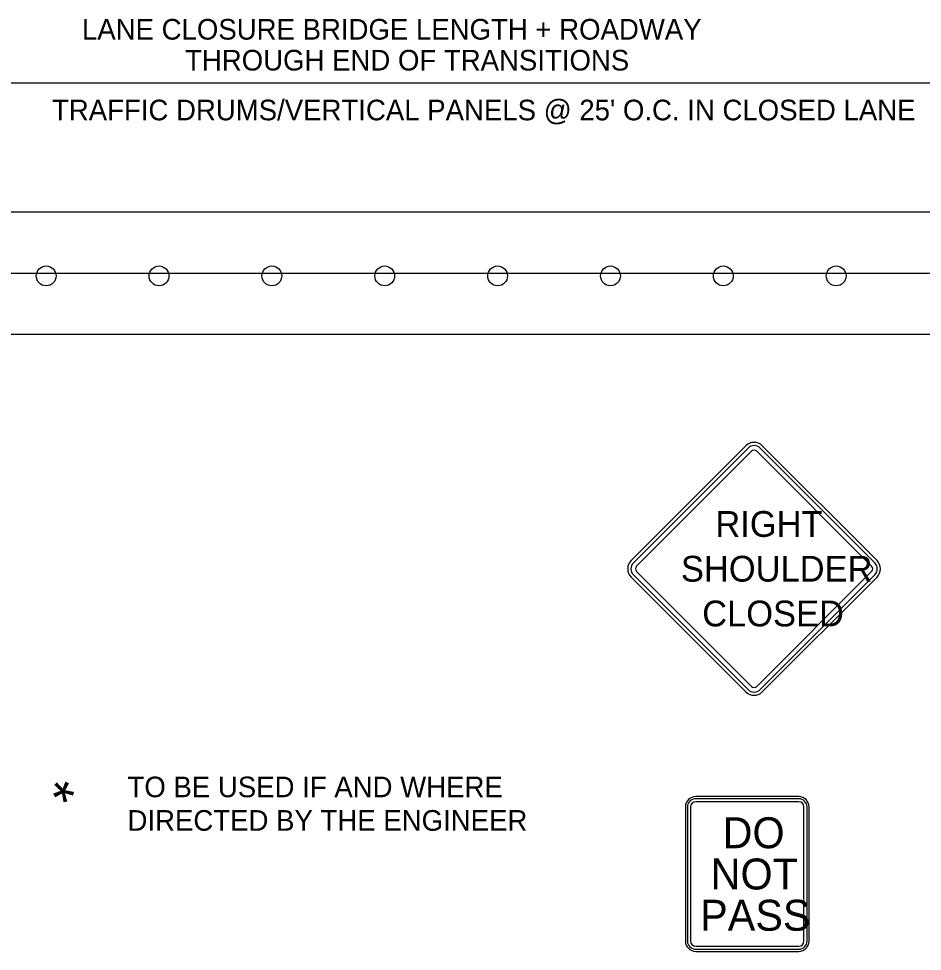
# Model space of a CAD drawing. Extents: x 1925873 to 1930787, y 596452 to 599617.
# Drawn here: x 1928470.6 to 1928733.6, y 597222 to 597493.3 of the extents above; entities that cross this region are included whole.
import ezdxf

# ---------------------------------------------------------------- set-up
doc = ezdxf.new("R2010")
doc.units = 0
for name, color, linetype in [('Default', 7, 'Continuous'), ('P_TC_Signs_Permanent', 7, 'Continuous'), ('P_TC_Signs_Temporary', 7, 'Continuous'), ('R_Border', 7, 'Continuous')]:
    doc.layers.add(name, color=color, linetype=linetype)

msp = doc.modelspace()

# ---------------------------------------------------------------- linework, layer by layer
at = {"layer": 'Default'}
for p, q in [((1928839.89, 597474.52), (1928347.22, 597474.52)), ((1927951.04, 597437.1), (1928839.89, 597437.1)), ((1927951.04, 597419.31), (1928839.89, 597419.31)), ((1927951.04, 597401.52), (1928839.89, 597401.52))]:
    msp.add_line(p, q, dxfattribs=at)
for centre in [(1928478.6, 597418.47), (1928511.44, 597418.47), (1928544.28, 597418.47), (1928577.13, 597418.47), (1928609.97, 597418.47), (1928642.82, 597418.47), (1928675.66, 597418.47), (1928708.51, 597418.47)]:
    msp.add_circle(centre, 2.88, dxfattribs=at)
at = {"layer": 'P_TC_Signs_Permanent'}
for p, q in [((1928697.62, 597267), (1928667.62, 597267)), ((1928697.62, 597266.4), (1928667.62, 597266.4)), ((1928664.62, 597264), (1928664.62, 597225)), ((1928665.22, 597264), (1928665.22, 597225)), ((1928666.12, 597264), (1928666.12, 597225)), ((1928697.62, 597265.5), (1928667.62, 597265.5)), ((1928699.12, 597225), (1928699.12, 597264)), ((1928700.02, 597225), (1928700.02, 597264)), ((1928700.62, 597225), (1928700.62, 597264)), ((1928667.62, 597223.5), (1928697.62, 597223.5)), ((1928667.62, 597222.6), (1928697.62, 597222.6)), ((1928667.62, 597222), (1928697.62, 597222))]:
    msp.add_line(p, q, dxfattribs=at)
for centre, radius, start, end in [((1928667.62, 597264), 3, 90, 180), ((1928667.62, 597264), 2.4, 90, 180), ((1928697.62, 597264), 3, 360, 90), ((1928697.62, 597264), 2.4, 360, 90), ((1928667.62, 597264), 1.5, 90, 180), ((1928697.62, 597264), 1.5, 360, 90), ((1928667.62, 597225), 3, 180, 270), ((1928667.62, 597225), 2.4, 180, 270), ((1928667.62, 597225), 1.5, 180, 270), ((1928697.62, 597225), 3, 270, 360), ((1928697.62, 597225), 2.4, 270, 360), ((1928697.62, 597225), 1.5, 270, 360)]:
    msp.add_arc(centre, radius, start, end, dxfattribs=at)
at = {"layer": 'P_TC_Signs_Temporary'}
for p, q in [((1928648.83, 597335.65), (1928682.24, 597369.06)), ((1928687.01, 597369.06), (1928720.42, 597335.65)), ((1928649.49, 597334.98), (1928682.9, 597368.39)), ((1928650.42, 597334.06), (1928683.83, 597367.47)), ((1928685.42, 597367.47), (1928718.83, 597334.06)), ((1928686.35, 597368.39), (1928719.76, 597334.98)), ((1928682.9, 597298.13), (1928649.49, 597331.54)), ((1928683.83, 597299.05), (1928650.42, 597332.46)), ((1928718.83, 597332.46), (1928685.42, 597299.05)), ((1928719.76, 597331.54), (1928686.35, 597298.13)), ((1928682.24, 597297.46), (1928648.83, 597330.87)), ((1928720.42, 597330.87), (1928687.01, 597297.46))]:
    msp.add_line(p, q, dxfattribs=at)
for centre, radius, start, end in [((1928684.62, 597366.67), 3.38, 45, 135), ((1928684.62, 597366.67), 2.44, 45, 135), ((1928684.62, 597366.67), 1.13, 45, 135), ((1928651.21, 597333.26), 3.37, 135, 225), ((1928651.21, 597333.26), 2.44, 135, 225), ((1928651.21, 597333.26), 1.12, 135, 225), ((1928718.03, 597333.26), 1.12, 315, 45), ((1928718.03, 597333.26), 2.44, 315, 45), ((1928718.03, 597333.26), 3.37, 315, 45), ((1928684.62, 597299.85), 1.13, 225, 315), ((1928684.62, 597299.85), 3.38, 225, 315), ((1928684.62, 597299.85), 2.44, 225, 315)]:
    msp.add_arc(centre, radius, start, end, dxfattribs=at)

# ---------------------------------------------------------------- texts
at = {"layer": 'Default'}
for s, p in [('LANE CLOSURE BRIDGE LENGTH + ROADWAY ', (1928489.02, 597487.2)), ('THROUGH END OF TRANSITIONS', (1928519.02, 597478.21)), ("TRAFFIC DRUMS/VERTICAL PANELS @ 25' O.C. IN CLOSED LANE", (1928480.29, 597463.72))]:
    msp.add_text(s, height=5.9996, rotation=360, dxfattribs=at).set_placement(p)
at = {"layer": 'P_TC_Signs_Permanent'}
for s, rotation, p in [('DO', 360, (1928675.45, 597252)), ('NOT', 359.9596, (1928671.97, 597240.01)), ('PASS', 360, (1928668.92, 597228))]:
    msp.add_text(s, height=9, rotation=rotation, dxfattribs=at).set_placement(p)
at = {"layer": 'P_TC_Signs_Temporary'}
for s, p in [('RIGHT', (1928673.35, 597342.56)), ('SHOULDER', (1928663.33, 597329.54)), ('CLOSED', (1928669.51, 597316.52))]:
    msp.add_text(s, height=7.5, rotation=360, dxfattribs=at).set_placement(p)
at = {"layer": 'R_Border'}
for s, height, rotation, p in [('*', 12, 45, (1928487.56, 597260.09)), ('TO BE USED IF AND WHERE', 6, 360, (1928502.27, 597266.83)), ('DIRECTED BY THE ENGINEER', 6, 360, (1928502.27, 597257.08))]:
    msp.add_text(s, height=height, rotation=rotation, dxfattribs=at).set_placement(p)

doc.saveas('drawing.dxf')
